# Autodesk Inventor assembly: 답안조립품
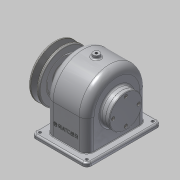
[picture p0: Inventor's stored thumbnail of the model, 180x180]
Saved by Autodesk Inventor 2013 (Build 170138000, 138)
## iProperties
Created: 2016-01
Part Number: 답안조립품
Document SubType Name: Assembly
Designer: Administrator
Author: Administrator
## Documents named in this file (15)
- C:\Users\Administrator\Desktop\460106V1024\답안조립품.iam
- C:\Users\Administrator\Desktop\460106V1024\본체.ipt
- C:\Users\Administrator\Desktop\460106V1024\베어링 6203.ipt
- C:\Users\Administrator\Desktop\460106V1024\뒤커버.ipt
- C:\Users\Administrator\Desktop\460106V1024\앞커버.ipt
- C:\Users\Administrator\Desktop\460106V1024\부시1.ipt
- C:\Users\Administrator\Desktop\460106V1024\축.ipt
- C:\Users\Administrator\Desktop\460106V1024\키 - 6 x 6 x 22.ipt
- C:\Users\Administrator\Desktop\460106V1024\스퍼기어.ipt
- C:\Users\Administrator\Desktop\460106V1024\키 - 5 x 5 x 18.ipt
- C:\Users\Administrator\Desktop\460106V1024\오일씰 28 40 8.ipt
- C:\Users\Administrator\Desktop\460106V1024\V-벨트풀리.ipt
- C:\Users\Administrator\Desktop\460106V1024\볼트 M3 x 8.ipt
- C:\Users\Administrator\Desktop\460106V1024\볼트 M3 x 10.ipt
- C:\Users\Administrator\Desktop\460106V1024\멈춤나사 - M4x10.ipt
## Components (9 placed, 3 different names)
1. V-벨트풀리:1
2. ISO 4762 M3 x 8:1
3. ISO 4762 M3 x 8:2
4. ISO 4762 M3 x 8:3
5. ISO 4762 M3 x 8:4
6. ISO 4762 M3 x 10:1
7. ISO 4762 M3 x 10:2
8. ISO 4762 M3 x 10:3
9. ISO 4762 M3 x 10:4
